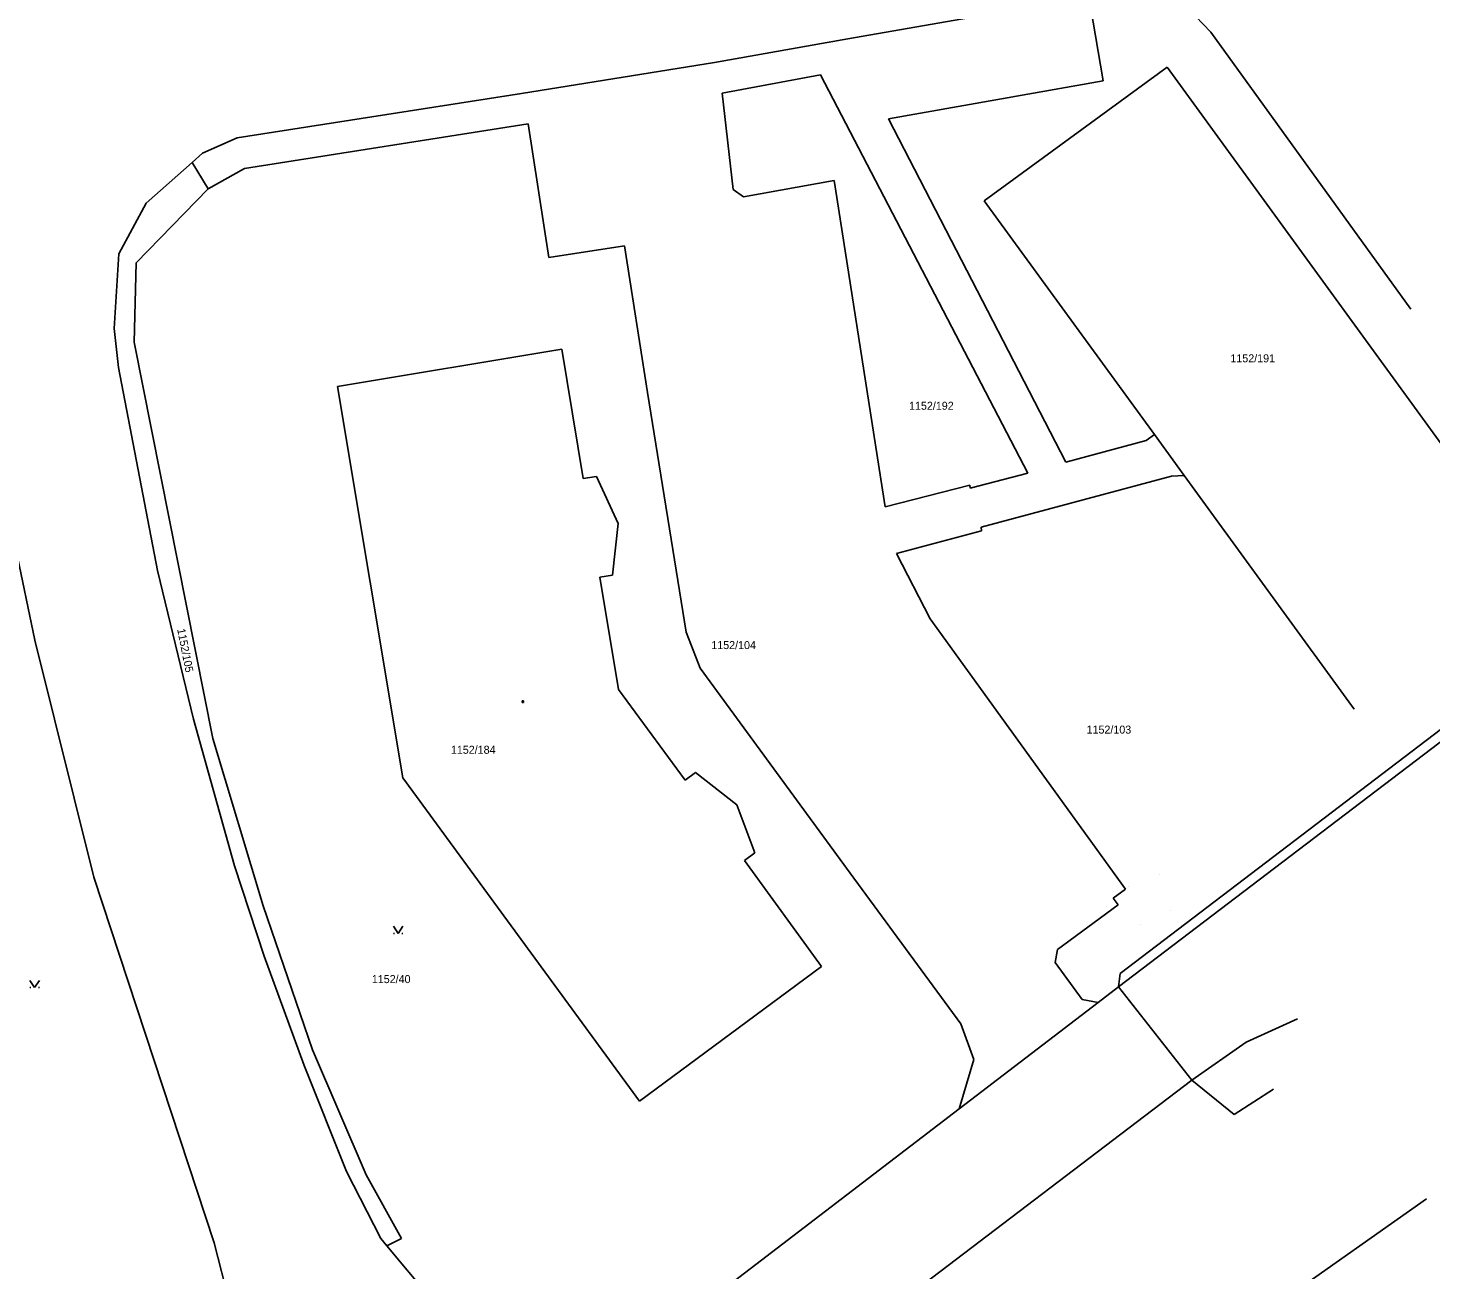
# Model space of a CAD drawing. Extents: x -609709 to -609357, y -1051535 to -1051131.
# Drawn here: x -609483.9 to -609409.4, y -1051454.5 to -1051388.6 of the extents above; entities that cross this region are included whole.
import ezdxf

# ---------------------------------------------------------------- set-up
doc = ezdxf.new("R2010")
doc.units = 0
doc.layers.add('Vrstva 10', color=7, linetype='Continuous')

msp = doc.modelspace()

# ---------------------------------------------------------------- linework, layer by layer
at = {"layer": 'Vrstva 10'}
for p, q in [((-609440.36, -1051389.16), (-609427.08, -1051386.84)), ((-609427.46, -1051387.44), (-609426.8, -1051391.39)), ((-609421.88, -1051387.95), (-609421.07, -1051388.81)), ((-609421.07, -1051388.81), (-609410.45, -1051403.51)), ((-609447.43, -1051390.41), (-609440.36, -1051389.16)), ((-609457.69, -1051392.06), (-609447.43, -1051390.41)), ((-609447.03, -1051392.04), (-609441.81, -1051391.08)), ((-609430.79, -1051412.22), (-609441.81, -1051391.08)), ((-609433.11, -1051397.76), (-609423.39, -1051390.67)), ((-609423.39, -1051390.67), (-609403.73, -1051417.7)), ((-609426.8, -1051391.39), (-609438.2, -1051393.41)), ((-609472.79, -1051394.42), (-609457.69, -1051392.06)), ((-609446.44, -1051397.16), (-609447.03, -1051392.04)), ((-609457.33, -1051393.67), (-609472.41, -1051396.04)), ((-609456.24, -1051400.78), (-609457.33, -1051393.67)), ((-609438.2, -1051393.41), (-609428.77, -1051411.65)), ((-609474.63, -1051395.23), (-609472.79, -1051394.42)), ((-609475.19, -1051395.73), (-609474.63, -1051395.23)), ((-609477.62, -1051397.89), (-609475.19, -1051395.73)), ((-609475.19, -1051395.73), (-609474.33, -1051397.12)), ((-609472.41, -1051396.04), (-609474.33, -1051397.12)), ((-609441.08, -1051396.69), (-609445.89, -1051397.56)), ((-609438.38, -1051414.02), (-609441.08, -1051396.69)), ((-609478.15, -1051401.06), (-609474.33, -1051397.12)), ((-609445.89, -1051397.56), (-609446.44, -1051397.16)), ((-609424.07, -1051410.18), (-609433.11, -1051397.76)), ((-609479.07, -1051400.58), (-609477.62, -1051397.89)), ((-609425.97, -1051439.51), (-609371.78, -1051398.25)), ((-609479.33, -1051404.55), (-609479.07, -1051400.58)), ((-609452.22, -1051400.15), (-609456.24, -1051400.78)), ((-609451, -1051407.94), (-609452.22, -1051400.15)), ((-609478.26, -1051405.27), (-609478.15, -1051401.06)), ((-609479.33, -1051404.55), (-609479.09, -1051406.62)), ((-609478.26, -1051405.27), (-609474.09, -1051426.32)), ((-609467.46, -1051407.63), (-609455.54, -1051405.64)), ((-609455.54, -1051405.64), (-609454.42, -1051412.51)), ((-609479.09, -1051406.62), (-609477.02, -1051417.4)), ((-609467.46, -1051407.63), (-609464, -1051428.41)), ((-609448.95, -1051420.67), (-609451, -1051407.94)), ((-609486.07, -1051409), (-609483.54, -1051421.1)), ((-609424.51, -1051410.5), (-609424.07, -1051410.18)), ((-609422.49, -1051412.35), (-609424.07, -1051410.18)), ((-609428.77, -1051411.65), (-609424.51, -1051410.5)), ((-609454.42, -1051412.51), (-609453.71, -1051412.4)), ((-609453.71, -1051412.4), (-609452.55, -1051414.9)), ((-609433.85, -1051413.03), (-609430.79, -1051412.22)), ((-609423.17, -1051412.39), (-609433.27, -1051415.1)), ((-609422.49, -1051412.35), (-609423.17, -1051412.39)), ((-609413.46, -1051424.76), (-609422.49, -1051412.35)), ((-609438.38, -1051414.02), (-609433.88, -1051412.86)), ((-609433.88, -1051412.86), (-609433.85, -1051413.03)), ((-609452.85, -1051417.64), (-609452.55, -1051414.9)), ((-609433.25, -1051415.29), (-609437.77, -1051416.5)), ((-609433.27, -1051415.1), (-609433.25, -1051415.29)), ((-609437.77, -1051416.5), (-609435.99, -1051419.97)), ((-609477.02, -1051417.4), (-609475.12, -1051425.29)), ((-609453.52, -1051417.75), (-609452.85, -1051417.64)), ((-609453.52, -1051417.75), (-609452.54, -1051423.71)), ((-609399.48, -1051418.68), (-609425.89, -1051438.8)), ((-609435.99, -1051419.97), (-609425.61, -1051434.33)), ((-609448.2, -1051422.58), (-609448.95, -1051420.67)), ((-609483.54, -1051421.1), (-609480.4, -1051433.68)), ((-609440.24, -1051433.47), (-609448.2, -1051422.58)), ((-609452.54, -1051423.71), (-609448.99, -1051428.53)), ((-609457.655, -1051424.325), (-609457.58, -1051424.325)), ((-609457.655, -1051424.4), (-609457.655, -1051424.325)), ((-609457.58, -1051424.4), (-609457.655, -1051424.4)), ((-609457.58, -1051424.325), (-609457.58, -1051424.4)), ((-609475.12, -1051425.29), (-609472.93, -1051433.08)), ((-609474.09, -1051426.32), (-609471.41, -1051435.21)), ((-609448.99, -1051428.53), (-609448.45, -1051428.13)), ((-609448.45, -1051428.13), (-609446.26, -1051429.85)), ((-609464, -1051428.41), (-609451.42, -1051445.59)), ((-609446.26, -1051429.85), (-609445.3, -1051432.4)), ((-609445.84, -1051432.8), (-609445.3, -1051432.4)), ((-609445.84, -1051432.8), (-609441.75, -1051438.43)), ((-609472.93, -1051433.08), (-609471.36, -1051437.88)), ((-609434.36, -1051441.48), (-609440.24, -1051433.47)), ((-609423.82, -1051433.53), (-609423.82, -1051433.53)), ((-609480.4, -1051433.68), (-609474.02, -1051453.1)), ((-609425.44, -1051434.17), (-609425.44, -1051434.17)), ((-609425.61, -1051434.33), (-609426.26, -1051434.8)), ((-609426.26, -1051434.8), (-609426, -1051435.16)), ((-609420.9, -1051435), (-609420.9, -1051435)), ((-609471.41, -1051435.21), (-609468.79, -1051442.85)), ((-609426, -1051435.16), (-609429.21, -1051437.53)), ((-609423.24, -1051435.46), (-609423.24, -1051435.46)), ((-609464.49, -1051436.295), (-609464.24, -1051436.67)), ((-609464.24, -1051436.67), (-609463.99, -1051436.295)), ((-609424.79, -1051436.22), (-609424.79, -1051436.22)), ((-609464.49, -1051436.67), (-609464.44, -1051436.67)), ((-609464.04, -1051436.67), (-609463.99, -1051436.67)), ((-609471.36, -1051437.88), (-609469.23, -1051443.68)), ((-609429.21, -1051437.53), (-609429.34, -1051438.22)), ((-609451.42, -1051445.59), (-609441.75, -1051438.43)), ((-609429.34, -1051438.22), (-609427.9, -1051440.18)), ((-609483.8, -1051439.165), (-609483.55, -1051439.54)), ((-609483.55, -1051439.54), (-609483.3, -1051439.165)), ((-609427.06, -1051440.34), (-609425.97, -1051439.51)), ((-609425.97, -1051439.51), (-609425.89, -1051438.8)), ((-609425.97, -1051439.51), (-609422.08, -1051444.46)), ((-609483.8, -1051439.54), (-609483.75, -1051439.54)), ((-609483.35, -1051439.54), (-609483.3, -1051439.54)), ((-609427.9, -1051440.18), (-609427.06, -1051440.34)), ((-609427.06, -1051440.34), (-609434.44, -1051445.99)), ((-609433.66, -1051443.36), (-609434.36, -1051441.48)), ((-609419.2, -1051442.44), (-609416.47, -1051441.2)), ((-609422.08, -1051444.46), (-609419.2, -1051442.44)), ((-609468.79, -1051442.85), (-609465.94, -1051449.49)), ((-609469.23, -1051443.68), (-609466.99, -1051449.31)), ((-609434.44, -1051445.99), (-609433.66, -1051443.36)), ((-609463.64, -1051476.07), (-609422.08, -1051444.46)), ((-609422.08, -1051444.46), (-609419.84, -1051446.29)), ((-609419.84, -1051446.29), (-609417.75, -1051444.94)), ((-609434.44, -1051445.99), (-609447.85, -1051456.25)), ((-609466.99, -1051449.31), (-609465.16, -1051452.88)), ((-609465.94, -1051449.49), (-609464.06, -1051452.88)), ((-609447.09, -1051477.17), (-609409.61, -1051450.76)), ((-609465.16, -1051452.88), (-609464.84, -1051453.26)), ((-609464.84, -1051453.26), (-609464.06, -1051452.88)), ((-609464.06, -1051452.88), (-609464.06, -1051452.88)), ((-609474.02, -1051453.1), (-609472.27, -1051459.87)), ((-609464.84, -1051453.26), (-609462.59, -1051455.96))]:
    msp.add_line(p, q, dxfattribs=at)

# ---------------------------------------------------------------- texts
for s, p in [('1152/191', (-609420.034, -1051406.34)), ('1152/192', (-609437.103, -1051408.86)), ('1152/104', (-609447.607, -1051421.57)), ('1152/103', (-609427.673, -1051426.06)), ('1152/184', (-609461.44, -1051427.13)), ('1152/40', (-609465.639, -1051439.31))]:
    msp.add_text(s, height=0.425, dxfattribs=at).set_placement(p)
msp.add_text('1152/105', height=0.425, rotation=281.17791, dxfattribs=at).set_placement((-609475.983, -1051420.518))

doc.saveas('drawing.dxf')
